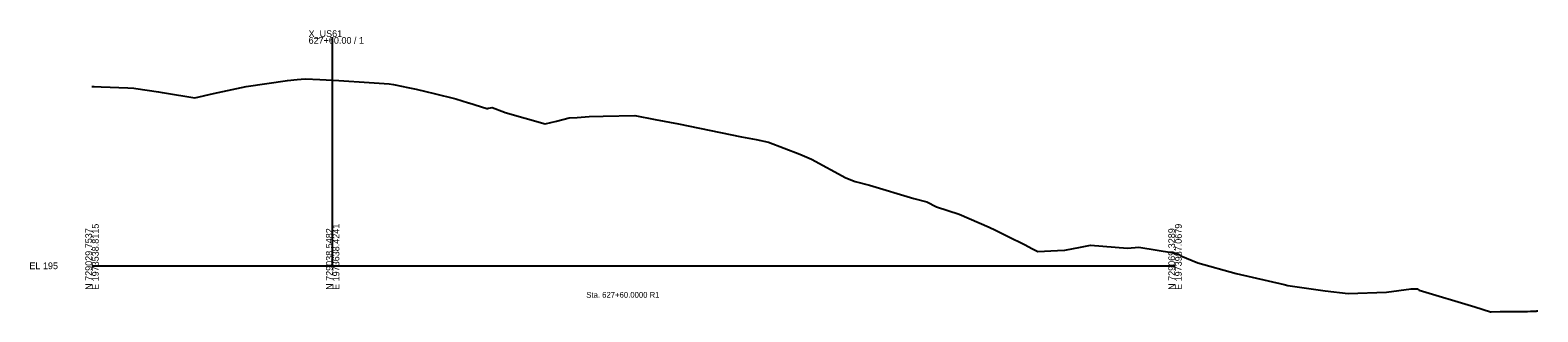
# Model space of a CAD drawing. Extents: x -26 to 630, y -39 to 9098.
# Drawn here: x -26 to 601, y 8981 to 9098 of the extents above; entities that cross this region are included whole.
import ezdxf

# ---------------------------------------------------------------- set-up
doc = ezdxf.new("R2010")
doc.units = 0
for name, color, linetype in [('Draft_XS_Grid', 7, 'Continuous'), ('Draft_XS_Text', 7, 'Continuous'), ('DTM_X_GROUND', 7, 'Continuous'), ('XS_CELL', 7, 'Continuous')]:
    doc.layers.add(name, color=color, linetype=linetype)

msp = doc.modelspace()

# ---------------------------------------------------------------- linework, layer by layer
at = {"layer": 'DTM_X_GROUND'}
msp.add_lwpolyline([(0, 9074.39), (0.92, 9074.4), (3.87, 9074.3), (14.89, 9073.95), (17.34, 9073.74), (18.23, 9073.66), (27.62, 9072.19), (29.15, 9071.93), (30.16, 9071.76), (42.67, 9069.76), (50.48, 9071.52), (64.08, 9074.52), (81.2, 9077), (85.22, 9077.41), (86.88, 9077.51), (88.69, 9077.63), (94.63, 9077.31), (102.6, 9076.88), (115.22, 9076.07), (123.52, 9075.54), (125.28, 9075.27), (126.01, 9075.16), (131.28, 9074.05), (134.69, 9073.33), (138.77, 9072.37), (142.2, 9071.51), (151.15, 9069.28), (156.41, 9067.73), (156.64, 9067.66), (164.08, 9065.26), (164.34, 9065.32), (164.36, 9065.33), (164.61, 9065.39), (164.62, 9065.39), (164.82, 9065.44), (164.95, 9065.47), (166.33, 9065.73), (171.37, 9063.78), (171.46, 9063.76), (171.68, 9063.69), (188.26, 9058.9), (192.95, 9060.1), (198.26, 9061.47), (201.58, 9061.62), (206.55, 9062.03), (212.36, 9062.07), (225.49, 9062.38), (233.98, 9060.77), (243.7, 9059), (269.92, 9053.61), (275.98, 9052.42), (281.04, 9051.34), (294.14, 9046.4), (298.97, 9044.29), (313.17, 9036.58), (317.12, 9035.05), (323.07, 9033.47), (341.41, 9027.97), (346.89, 9026.57), (350.89, 9024.43), (360.3, 9021.47), (372.77, 9016.06), (375.38, 9014.79), (380.66, 9012.2), (387.47, 9008.87), (390.78, 9007.08), (392.95, 9005.95), (401.1, 9006.29), (404.28, 9006.43), (410.68, 9007.73), (414.93, 9008.59), (430.28, 9007.32), (434.95, 9007.71), (449.43, 9005.42), (451.54, 9004.66), (452.46, 9004.21), (459.51, 9001.24), (475.41, 8996.75), (495.35, 8992.2), (496.85, 8991.88), (497.8, 8991.73), (512.32, 8989.64), (521.93, 8988.51), (537.92, 8989.05), (548.13, 8990.37), (550.54, 8990.5), (551.44, 8989.91), (574.61, 8983.02), (581.03, 8980.89), (581.34, 8980.9), (581.42, 8980.9), (585.13, 8980.97), (589.01, 8981), (590.56, 8981.03), (594.02, 8981.07), (596.49, 8981.09), (597.76, 8981.14), (598.79, 8981.18), (599.63, 8981.21), (600.05, 8981.23), (600.32, 8981.26), (600.55, 8981.28), (600.75, 8981.3)], dxfattribs=at)
at = {"layer": 'XS_CELL'}
for p, q in [((100, 9000), (100, 9095)), ((0, 9000), (100, 9000)), ((100, 9000), (450, 9000))]:
    msp.add_line(p, q, dxfattribs=at)

# ---------------------------------------------------------------- texts
at = {"layer": 'Draft_XS_Grid'}
msp.add_text('-', height=0.0001, dxfattribs=at).set_placement((0, 9000))
at = {"layer": 'Draft_XS_Text'}
msp.add_text('Sta. 627+60.0000 R1', height=2.4, dxfattribs=at).set_placement((205.37, 8986.75))
at = {"layer": 'XS_CELL'}
for s, p in [('X_US61', (90, 9095)), ('627+60.00 / 1', (90, 9092.2)), ('EL 195', (-26, 8998.6))]:
    msp.add_text(s, height=2.8, dxfattribs=at).set_placement(p)
for s, p in [('N 729029.7537', (0, 8990)), ('E 1973538.8115', (2.8, 8990)), ('N 729038.5482', (100, 8990)), ('E 1973638.4241', (102.8, 8990)), ('N 729069.3289', (450, 8990)), ('E 1973987.0679', (452.8, 8990))]:
    msp.add_text(s, height=2.8, rotation=90, dxfattribs=at).set_placement(p)

doc.saveas('drawing.dxf')
